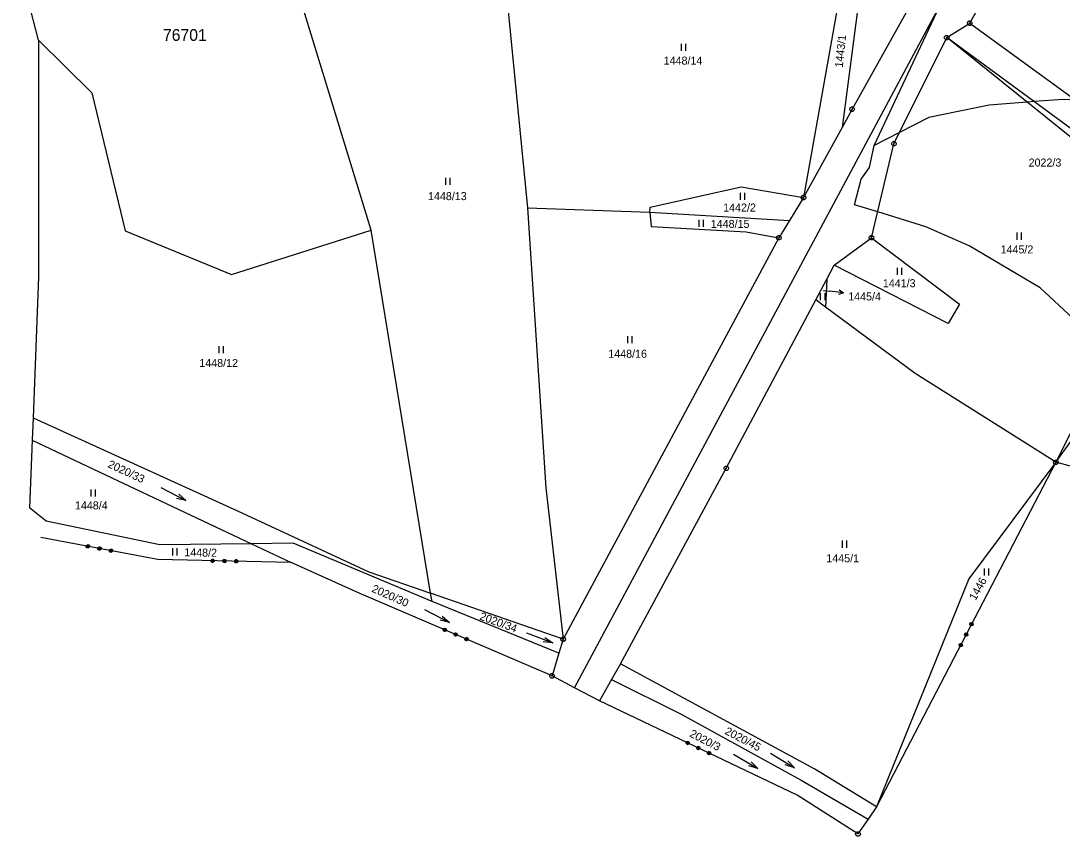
# Model space of a CAD drawing. Extents: x -789470 to -786707, y -1118640 to -1114455.
# Drawn here: x -787437 to -787215.8, y -1118639.9 to -1118466.7 of the extents above; entities that cross this region are included whole.
import ezdxf

# ---------------------------------------------------------------- set-up
doc = ezdxf.new("R2010")
doc.units = 0
for name, color, linetype in [('1', 7, 'Continuous'), ('11', 7, 'Continuous'), ('2', 7, 'Continuous'), ('3', 7, 'Continuous'), ('6', 7, 'Continuous'), ('7', 7, 'Continuous'), ('8', 7, 'Continuous')]:
    doc.layers.add(name, color=color, linetype=linetype)

msp = doc.modelspace()

# ---------------------------------------------------------------- linework, layer by layer
at = {"layer": '1'}
for p, q in [((-787362.53, -1118511.14), (-787390.51, -1118419.78)), ((-787433.19, -1118470.77), (-787443.96, -1118428.82)), ((-787235.39, -1118467.18), (-787217.86, -1118435.86)), ((-787261.35, -1118451.77), (-787270.69, -1118504.24)), ((-787258.06, -1118455.25), (-787262.52, -1118489.37)), ((-787334.09, -1118457.75), (-787329.35, -1118506.42)), ((-787248.91, -1118464.91), (-787260.38, -1118485.47)), ((-787240.28, -1118470.25), (-787235.39, -1118467.18)), ((-787235.39, -1118467.18), (-787210.21, -1118485.49)), ((-787433.19, -1118470.77), (-787433.23, -1118521.06)), ((-787433.19, -1118470.77), (-787421.86, -1118481.96)), ((-787251.49, -1118492.81), (-787240.28, -1118470.25)), ((-787213.6, -1118489.81), (-787240.28, -1118470.25)), ((-787213.08, -1118492.14), (-787240.28, -1118470.25)), ((-787421.86, -1118481.96), (-787414.81, -1118511.34)), ((-787260.38, -1118485.47), (-787262.52, -1118489.37)), ((-787262.52, -1118489.37), (-787270.69, -1118504.24)), ((-787256.27, -1118512.79), (-787251.49, -1118492.81)), ((-787186.43, -1118499.08), (-787217.11, -1118560.49)), ((-787303.28, -1118506.29), (-787283.94, -1118501.92)), ((-787283.94, -1118501.92), (-787270.69, -1118504.24)), ((-787270.69, -1118504.24), (-787273.7, -1118509.14)), ((-787329.35, -1118506.42), (-787303.31, -1118507.31)), ((-787329.35, -1118506.42), (-787325.42, -1118565.9)), ((-787303.31, -1118507.31), (-787303.28, -1118506.29)), ((-787303.31, -1118507.31), (-787303.09, -1118510.36)), ((-787303.31, -1118507.31), (-787273.7, -1118509.14)), ((-787303.09, -1118510.36), (-787282.85, -1118511.55)), ((-787273.7, -1118509.14), (-787275.95, -1118512.79)), ((-787414.81, -1118511.34), (-787392.19, -1118520.57)), ((-787392.19, -1118520.57), (-787362.53, -1118511.14)), ((-787349.9, -1118588.32), (-787362.53, -1118511.14)), ((-787275.95, -1118512.79), (-787321.76, -1118598.1)), ((-787282.85, -1118511.55), (-787275.95, -1118512.79)), ((-787264.16, -1118518.6), (-787256.27, -1118512.79)), ((-787256.27, -1118512.79), (-787237.55, -1118526.92)), ((-787265.75, -1118521.6), (-787264.16, -1118518.6)), ((-787240, -1118531.03), (-787264.16, -1118518.6)), ((-787433.23, -1118521.06), (-787434.36, -1118551.03)), ((-787268.09, -1118526), (-787265.75, -1118521.6)), ((-787265.75, -1118521.6), (-787266.06, -1118527.5)), ((-787287.1, -1118561.77), (-787268.09, -1118526)), ((-787266.06, -1118527.5), (-787268.09, -1118526)), ((-787246.95, -1118541.62), (-787266.06, -1118527.5)), ((-787237.55, -1118526.92), (-787240, -1118531.03)), ((-787217.11, -1118560.49), (-787200.96, -1118538.1)), ((-787217.11, -1118560.49), (-787246.95, -1118541.62)), ((-787434.36, -1118551.03), (-787434.54, -1118555.77)), ((-787434.36, -1118551.03), (-787390.92, -1118570.77)), ((-787434.54, -1118555.77), (-787435.08, -1118570.18)), ((-787434.54, -1118555.77), (-787387.94, -1118577.81)), ((-787309.57, -1118603.31), (-787287.1, -1118561.77)), ((-787217.11, -1118560.49), (-787255.19, -1118633.7)), ((-787217.11, -1118560.49), (-787235.57, -1118585.27)), ((-787213.48, -1118561.45), (-787217.11, -1118560.49)), ((-787325.42, -1118565.9), (-787321.76, -1118598.1)), ((-787431.54, -1118573.02), (-787435.08, -1118570.18)), ((-787390.92, -1118570.77), (-787363.02, -1118583.76)), ((-787407.41, -1118578.04), (-787431.54, -1118573.02)), ((-787407.83, -1118581.15), (-787432.67, -1118576.48)), ((-787387.94, -1118577.81), (-787407.41, -1118578.04)), ((-787379.13, -1118577.71), (-787387.94, -1118577.81)), ((-787387.94, -1118577.81), (-787379.56, -1118581.78)), ((-787349.61, -1118590.09), (-787379.13, -1118577.71)), ((-787379.56, -1118581.78), (-787407.83, -1118581.15)), ((-787365.06, -1118588.3), (-787379.56, -1118581.78)), ((-787363.02, -1118583.76), (-787349.9, -1118588.32)), ((-787235.57, -1118585.27), (-787255.19, -1118633.7)), ((-787324.12, -1118605.87), (-787365.06, -1118588.3)), ((-787349.61, -1118590.09), (-787349.9, -1118588.32)), ((-787321.76, -1118598.1), (-787349.9, -1118588.32)), ((-787322.66, -1118601.06), (-787349.61, -1118590.09)), ((-787321.76, -1118598.1), (-787322.66, -1118601.06)), ((-787322.66, -1118601.06), (-787324.12, -1118605.87)), ((-787309.57, -1118603.31), (-787311.47, -1118606.64)), ((-787268.28, -1118625.73), (-787309.57, -1118603.31)), ((-787319.31, -1118608.45), (-787324.12, -1118605.87)), ((-787311.47, -1118606.64), (-787314.06, -1118611.19)), ((-787311.47, -1118606.64), (-787296.71, -1118614.01)), ((-787314.06, -1118611.19), (-787319.31, -1118608.45)), ((-787272.02, -1118631.21), (-787314.06, -1118611.19)), ((-787296.71, -1118614.01), (-787271.2, -1118628.01)), ((-787255.19, -1118633.7), (-787268.28, -1118625.73)), ((-787271.2, -1118628.01), (-787257, -1118636.34)), ((-787259.14, -1118639.46), (-787272.02, -1118631.21)), ((-787255.19, -1118633.7), (-787257, -1118636.34)), ((-787257, -1118636.34), (-787259.14, -1118639.46))]:
    msp.add_line(p, q, dxfattribs=at)
for points in [[(-787422.91, -1118578.64), (-787423.07, -1118578.42), (-787423.02, -1118578.15), (-787422.79, -1118578), (-787422.53, -1118578.05), (-787422.38, -1118578.27), (-787422.43, -1118578.54), (-787422.65, -1118578.69), (-787422.91, -1118578.64), (-787422.87, -1118578.61), (-787422.63, -1118578.65), (-787422.56, -1118578.59), (-787422.93, -1118578.52), (-787422.99, -1118578.42), (-787422.48, -1118578.52), (-787422.47, -1118578.44), (-787422.98, -1118578.34), (-787422.97, -1118578.26), (-787422.45, -1118578.36), (-787422.43, -1118578.28), (-787422.94, -1118578.19), (-787422.89, -1118578.12), (-787422.48, -1118578.19), (-787422.52, -1118578.1), (-787422.75, -1118578.06)], [(-787420.45, -1118579.1), (-787420.6, -1118578.88), (-787420.55, -1118578.62), (-787420.33, -1118578.46), (-787420.06, -1118578.51), (-787419.91, -1118578.74), (-787419.96, -1118579), (-787420.18, -1118579.15), (-787420.45, -1118579.1), (-787420.43, -1118579.07), (-787420.19, -1118579.11), (-787420.1, -1118579.05), (-787420.49, -1118578.97), (-787420.56, -1118578.88), (-787420.01, -1118578.98), (-787419.99, -1118578.9), (-787420.54, -1118578.8), (-787420.53, -1118578.72), (-787419.98, -1118578.83), (-787419.96, -1118578.75), (-787420.51, -1118578.64), (-787420.42, -1118578.58), (-787420.03, -1118578.65), (-787420.09, -1118578.56), (-787420.33, -1118578.52)], [(-787417.98, -1118579.57), (-787418.13, -1118579.35), (-787418.08, -1118579.08), (-787417.86, -1118578.93), (-787417.59, -1118578.98), (-787417.44, -1118579.2), (-787417.49, -1118579.46), (-787417.71, -1118579.62), (-787417.98, -1118579.57), (-787417.98, -1118579.53), (-787417.75, -1118579.57), (-787417.65, -1118579.51), (-787418.05, -1118579.43), (-787418.09, -1118579.34), (-787417.56, -1118579.44), (-787417.54, -1118579.36), (-787418.07, -1118579.27), (-787418.06, -1118579.19), (-787417.54, -1118579.28), (-787417.53, -1118579.2), (-787418.05, -1118579.11), (-787417.98, -1118579.04), (-787417.56, -1118579.12), (-787417.61, -1118579.03), (-787417.89, -1118578.97)], [(-787396.35, -1118581.73), (-787396.54, -1118581.53), (-787396.53, -1118581.26), (-787396.34, -1118581.08), (-787396.07, -1118581.08), (-787395.88, -1118581.28), (-787395.89, -1118581.55), (-787396.08, -1118581.73), (-787396.35, -1118581.73), (-787396.31, -1118581.69), (-787396.07, -1118581.69), (-787396.01, -1118581.61), (-787396.39, -1118581.6), (-787396.47, -1118581.52), (-787395.95, -1118581.53), (-787395.95, -1118581.45), (-787396.47, -1118581.44), (-787396.46, -1118581.36), (-787395.94, -1118581.37), (-787395.93, -1118581.29), (-787396.45, -1118581.28), (-787396.41, -1118581.2), (-787396, -1118581.21), (-787396.05, -1118581.13), (-787396.29, -1118581.13)], [(-787393.84, -1118581.78), (-787394.03, -1118581.59), (-787394.02, -1118581.32), (-787393.83, -1118581.13), (-787393.56, -1118581.14), (-787393.37, -1118581.33), (-787393.38, -1118581.6), (-787393.57, -1118581.79), (-787393.84, -1118581.78), (-787393.83, -1118581.74), (-787393.59, -1118581.75), (-787393.51, -1118581.67), (-787393.91, -1118581.66), (-787393.99, -1118581.58), (-787393.43, -1118581.59), (-787393.43, -1118581.51), (-787393.99, -1118581.5), (-787393.98, -1118581.42), (-787393.42, -1118581.43), (-787393.42, -1118581.35), (-787393.98, -1118581.34), (-787393.9, -1118581.26), (-787393.5, -1118581.27), (-787393.58, -1118581.19), (-787393.82, -1118581.18)], [(-787391.33, -1118581.84), (-787391.52, -1118581.64), (-787391.51, -1118581.37), (-787391.32, -1118581.19), (-787391.05, -1118581.19), (-787390.86, -1118581.39), (-787390.87, -1118581.66), (-787391.06, -1118581.84), (-787391.33, -1118581.84), (-787391.34, -1118581.8), (-787391.1, -1118581.8), (-787391.02, -1118581.73), (-787391.42, -1118581.72), (-787391.48, -1118581.64), (-787390.94, -1118581.65), (-787390.94, -1118581.57), (-787391.47, -1118581.56), (-787391.47, -1118581.48), (-787390.94, -1118581.49), (-787390.94, -1118581.41), (-787391.47, -1118581.4), (-787391.42, -1118581.32), (-787390.99, -1118581.33), (-787391.06, -1118581.24), (-787391.34, -1118581.24)], [(-787234.77, -1118595.14), (-787235.03, -1118595.22), (-787235.27, -1118595.1), (-787235.35, -1118594.84), (-787235.23, -1118594.6), (-787234.97, -1118594.52), (-787234.73, -1118594.64), (-787234.65, -1118594.9), (-787234.77, -1118595.14), (-787234.81, -1118595.13), (-787234.7, -1118594.92), (-787234.74, -1118594.81), (-787234.92, -1118595.16), (-787235.02, -1118595.18), (-787234.77, -1118594.7), (-787234.84, -1118594.66), (-787235.09, -1118595.13), (-787235.16, -1118595.11), (-787234.92, -1118594.64), (-787234.99, -1118594.6), (-787235.23, -1118595.07), (-787235.28, -1118594.99), (-787235.08, -1118594.61), (-787235.19, -1118594.63), (-787235.31, -1118594.88)], [(-787347.15, -1118596.33), (-787347.25, -1118596.08), (-787347.14, -1118595.84), (-787346.89, -1118595.74), (-787346.65, -1118595.84), (-787346.55, -1118596.09), (-787346.65, -1118596.34), (-787346.9, -1118596.44), (-787347.15, -1118596.33), (-787347.1, -1118596.31), (-787346.88, -1118596.41), (-787346.79, -1118596.36), (-787347.14, -1118596.21), (-787347.18, -1118596.1), (-787346.7, -1118596.31), (-787346.67, -1118596.23), (-787347.15, -1118596.03), (-787347.12, -1118595.96), (-787346.64, -1118596.16), (-787346.6, -1118596.09), (-787347.08, -1118595.89), (-787347.01, -1118595.83), (-787346.63, -1118595.99), (-787346.65, -1118595.9), (-787346.87, -1118595.8)], [(-787344.84, -1118597.32), (-787344.94, -1118597.07), (-787344.84, -1118596.83), (-787344.59, -1118596.73), (-787344.34, -1118596.83), (-787344.24, -1118597.08), (-787344.35, -1118597.33), (-787344.6, -1118597.43), (-787344.84, -1118597.32), (-787344.82, -1118597.29), (-787344.6, -1118597.39), (-787344.49, -1118597.34), (-787344.86, -1118597.19), (-787344.9, -1118597.08), (-787344.39, -1118597.3), (-787344.36, -1118597.23), (-787344.87, -1118597.01), (-787344.84, -1118596.93), (-787344.33, -1118597.15), (-787344.29, -1118597.08), (-787344.81, -1118596.86), (-787344.7, -1118596.82), (-787344.34, -1118596.98), (-787344.38, -1118596.87), (-787344.6, -1118596.78)], [(-787235.93, -1118597.37), (-787236.19, -1118597.45), (-787236.43, -1118597.32), (-787236.51, -1118597.07), (-787236.38, -1118596.83), (-787236.13, -1118596.75), (-787235.89, -1118596.87), (-787235.81, -1118597.13), (-787235.93, -1118597.37), (-787235.96, -1118597.34), (-787235.85, -1118597.13), (-787235.88, -1118597.02), (-787236.07, -1118597.37), (-787236.18, -1118597.41), (-787235.92, -1118596.91), (-787235.99, -1118596.87), (-787236.25, -1118597.37), (-787236.32, -1118597.33), (-787236.06, -1118596.84), (-787236.13, -1118596.8), (-787236.39, -1118597.3), (-787236.42, -1118597.19), (-787236.24, -1118596.83), (-787236.35, -1118596.87), (-787236.46, -1118597.08)], [(-787342.54, -1118598.31), (-787342.64, -1118598.06), (-787342.53, -1118597.82), (-787342.28, -1118597.72), (-787342.03, -1118597.82), (-787341.93, -1118598.07), (-787342.04, -1118598.32), (-787342.29, -1118598.42), (-787342.54, -1118598.31), (-787342.53, -1118598.27), (-787342.31, -1118598.37), (-787342.21, -1118598.33), (-787342.57, -1118598.17), (-787342.6, -1118598.07), (-787342.1, -1118598.28), (-787342.07, -1118598.21), (-787342.56, -1118598), (-787342.53, -1118597.92), (-787342.05, -1118598.13), (-787342.02, -1118598.06), (-787342.5, -1118597.85), (-787342.43, -1118597.8), (-787342.03, -1118597.97), (-787342.06, -1118597.87), (-787342.32, -1118597.75)], [(-787237.09, -1118599.59), (-787237.34, -1118599.67), (-787237.58, -1118599.55), (-787237.67, -1118599.29), (-787237.54, -1118599.05), (-787237.28, -1118598.97), (-787237.04, -1118599.1), (-787236.96, -1118599.35), (-787237.09, -1118599.59), (-787237.11, -1118599.54), (-787236.99, -1118599.33), (-787237.04, -1118599.24), (-787237.21, -1118599.57), (-787237.32, -1118599.61), (-787237.08, -1118599.15), (-787237.15, -1118599.11), (-787237.39, -1118599.57), (-787237.46, -1118599.53), (-787237.22, -1118599.07), (-787237.29, -1118599.03), (-787237.53, -1118599.49), (-787237.58, -1118599.42), (-787237.39, -1118599.05), (-787237.49, -1118599.06), (-787237.6, -1118599.27)], [(-787295.57, -1118620.35), (-787295.66, -1118620.1), (-787295.54, -1118619.85), (-787295.29, -1118619.76), (-787295.05, -1118619.88), (-787294.96, -1118620.13), (-787295.07, -1118620.38), (-787295.33, -1118620.47), (-787295.57, -1118620.35), (-787295.52, -1118620.33), (-787295.3, -1118620.43), (-787295.21, -1118620.39), (-787295.55, -1118620.22), (-787295.59, -1118620.12), (-787295.12, -1118620.34), (-787295.09, -1118620.27), (-787295.56, -1118620.04), (-787295.52, -1118619.97), (-787295.05, -1118620.2), (-787295.01, -1118620.13), (-787295.48, -1118619.9), (-787295.41, -1118619.85), (-787295.04, -1118620.03), (-787295.05, -1118619.93), (-787295.27, -1118619.83)], [(-787293.3, -1118621.43), (-787293.39, -1118621.18), (-787293.28, -1118620.93), (-787293.02, -1118620.84), (-787292.78, -1118620.96), (-787292.69, -1118621.21), (-787292.81, -1118621.45), (-787293.06, -1118621.54), (-787293.3, -1118621.43), (-787293.28, -1118621.4), (-787293.06, -1118621.5), (-787292.95, -1118621.46), (-787293.32, -1118621.29), (-787293.35, -1118621.18), (-787292.85, -1118621.42), (-787292.81, -1118621.35), (-787293.32, -1118621.11), (-787293.28, -1118621.04), (-787292.78, -1118621.28), (-787292.74, -1118621.21), (-787293.25, -1118620.97), (-787293.14, -1118620.93), (-787292.78, -1118621.1), (-787292.82, -1118620.99), (-787293.04, -1118620.89)], [(-787291.04, -1118622.51), (-787291.13, -1118622.25), (-787291.01, -1118622.01), (-787290.76, -1118621.92), (-787290.51, -1118622.04), (-787290.42, -1118622.29), (-787290.54, -1118622.53), (-787290.79, -1118622.62), (-787291.04, -1118622.51), (-787291.03, -1118622.47), (-787290.81, -1118622.57), (-787290.71, -1118622.53), (-787291.07, -1118622.36), (-787291.09, -1118622.26), (-787290.6, -1118622.5), (-787290.57, -1118622.42), (-787291.04, -1118622.2), (-787291.02, -1118622.12), (-787290.54, -1118622.35), (-787290.51, -1118622.27), (-787290.98, -1118622.05), (-787290.9, -1118622), (-787290.52, -1118622.18), (-787290.55, -1118622.08), (-787290.8, -1118621.96)]]:
    msp.add_lwpolyline(points, dxfattribs=at)
at = {"layer": '11'}
for points in [[(-787255.68, -1118493.19), (-787233.59, -1118446.04), (-787230.84, -1118438.51)], [(-787112.79, -1118512.95), (-787130.07, -1118506.17), (-787135.15, -1118504.08), (-787145.45, -1118499.82), (-787158.51, -1118494.43), (-787159.84, -1118493.88), (-787176.24, -1118488.75), (-787197.75, -1118484.31), (-787212.94, -1118483.51), (-787215.54, -1118483.37), (-787221.72, -1118483.85), (-787223.23, -1118483.97), (-787231.26, -1118484.6), (-787244.06, -1118487.19), (-787250.3, -1118490.41), (-787255.68, -1118493.19)], [(-787199.3, -1118569.06), (-787198.55, -1118559.16), (-787201.19, -1118547.24), (-787201.87, -1118545.79), (-787203.36, -1118542.58), (-787203.59, -1118542.09), (-787203.72, -1118541.93), (-787206.27, -1118538.79), (-787213.43, -1118529.96), (-787220.46, -1118523.41), (-787235.48, -1118514.51), (-787244.7, -1118510.43), (-787254.95, -1118507.27), (-787259.84, -1118505.76), (-787258.42, -1118500.3), (-787256.65, -1118497.82), (-787255.68, -1118493.19)], [(-787199.3, -1118569.06), (-787210.97, -1118562.12), (-787213.48, -1118561.45), (-787217.11, -1118560.49), (-787255.19, -1118633.7), (-787257, -1118636.34), (-787259.14, -1118639.46), (-787272.02, -1118631.21), (-787314.06, -1118611.19), (-787319.31, -1118608.45), (-787324.12, -1118605.87), (-787365.06, -1118588.3), (-787379.56, -1118581.78), (-787407.83, -1118581.15), (-787432.67, -1118576.48)]]:
    msp.add_lwpolyline(points, dxfattribs=at)
at = {"layer": '3'}
for p, q in [((-787296.69, -1118471.59), (-787296.69, -1118473.09)), ((-787295.69, -1118473.09), (-787295.69, -1118471.59)), ((-787346.72, -1118500.03), (-787346.72, -1118501.53)), ((-787345.72, -1118501.53), (-787345.72, -1118500.03)), ((-787284.14, -1118503.25), (-787284.14, -1118504.75)), ((-787283.14, -1118504.75), (-787283.14, -1118503.25)), ((-787292.97, -1118508.97), (-787292.97, -1118510.47)), ((-787291.97, -1118510.47), (-787291.97, -1118508.97)), ((-787225.42, -1118511.69), (-787225.42, -1118513.19)), ((-787224.42, -1118513.19), (-787224.42, -1118511.69)), ((-787250.81, -1118519.19), (-787250.81, -1118520.69)), ((-787249.81, -1118520.69), (-787249.81, -1118519.19)), ((-787267.13, -1118524.52), (-787267.13, -1118526.02)), ((-787266.13, -1118526.02), (-787266.13, -1118524.52)), ((-787308.1, -1118533.7), (-787308.1, -1118535.2)), ((-787307.1, -1118535.2), (-787307.1, -1118533.7)), ((-787394.92, -1118535.82), (-787394.92, -1118537.32)), ((-787393.92, -1118537.32), (-787393.92, -1118535.82)), ((-787422.06, -1118566.28), (-787422.06, -1118567.78)), ((-787421.06, -1118567.78), (-787421.06, -1118566.28)), ((-787407.21, -1118565.88), (-787401.87, -1118568.62)), ((-787262.49, -1118577.14), (-787262.49, -1118578.64)), ((-787261.49, -1118578.64), (-787261.49, -1118577.14)), ((-787404.76, -1118578.77), (-787404.76, -1118580.27)), ((-787403.76, -1118580.27), (-787403.76, -1118578.77)), ((-787232.35, -1118583.06), (-787232.35, -1118584.56)), ((-787231.35, -1118584.56), (-787231.35, -1118583.06)), ((-787351.22, -1118591.79), (-787345.9, -1118594.55)), ((-787329.56, -1118596.74), (-787323.94, -1118598.86)), ((-787285.54, -1118622.54), (-787280.38, -1118625.58)), ((-787277.73, -1118622.27), (-787272.61, -1118625.41))]:
    msp.add_line(p, q, dxfattribs=at)
for points in [[(-787403.42, -1118567.26), (-787401.87, -1118568.62), (-787403.88, -1118568.15)], [(-787347.44, -1118593.19), (-787345.9, -1118594.55), (-787347.9, -1118594.07)], [(-787325.64, -1118597.69), (-787323.94, -1118598.86), (-787325.99, -1118598.62)], [(-787281.84, -1118624.14), (-787280.38, -1118625.58), (-787282.35, -1118625)], [(-787274.06, -1118623.94), (-787272.61, -1118625.41), (-787274.58, -1118624.79)]]:
    msp.add_lwpolyline(points, dxfattribs=at)
at = {"layer": '6'}
msp.add_line((-787319.31, -1118608.45), (-787222.61, -1118427.68), dxfattribs=at)
at = {"layer": '7'}
for p in [(-787266.47, -1118523.95), (-787262.22, -1118524.48)]:
    msp.add_line(p, (-787265.2, -1118524.11), dxfattribs=at)
msp.add_lwpolyline([(-787263.15, -1118523.86), (-787262.22, -1118524.48), (-787263.28, -1118524.85)], dxfattribs=at)
at = {"layer": '8'}
for p, q in [((-787235.51, -1118467.18), (-787235.27, -1118467.18)), ((-787240.4, -1118470.25), (-787240.16, -1118470.25)), ((-787260.5, -1118485.47), (-787260.26, -1118485.47)), ((-787251.61, -1118492.81), (-787251.37, -1118492.81)), ((-787270.81, -1118504.24), (-787270.57, -1118504.24)), ((-787276.07, -1118512.79), (-787275.83, -1118512.79)), ((-787256.39, -1118512.79), (-787256.15, -1118512.79)), ((-787287.22, -1118561.77), (-787286.98, -1118561.77)), ((-787217.23, -1118560.49), (-787216.99, -1118560.49)), ((-787321.88, -1118598.1), (-787321.64, -1118598.1)), ((-787324.24, -1118605.87), (-787324, -1118605.87)), ((-787259.02, -1118639.46), (-787259.26, -1118639.46))]:
    msp.add_line(p, q, dxfattribs=at)
for points in [[(-787235.24, -1118466.7), (-787234.99, -1118466.88), (-787234.89, -1118467.17), (-787234.99, -1118467.46), (-787235.24, -1118467.64), (-787235.55, -1118467.64), (-787235.8, -1118467.46), (-787235.9, -1118467.17), (-787235.8, -1118466.88), (-787235.55, -1118466.7)], [(-787240.13, -1118469.77), (-787239.88, -1118469.95), (-787239.78, -1118470.24), (-787239.88, -1118470.53), (-787240.13, -1118470.71), (-787240.44, -1118470.71), (-787240.69, -1118470.53), (-787240.79, -1118470.24), (-787240.69, -1118469.95), (-787240.44, -1118469.77)], [(-787260.23, -1118484.99), (-787259.98, -1118485.17), (-787259.88, -1118485.46), (-787259.98, -1118485.75), (-787260.23, -1118485.93), (-787260.54, -1118485.93), (-787260.79, -1118485.75), (-787260.89, -1118485.46), (-787260.79, -1118485.17), (-787260.54, -1118484.99)], [(-787251.34, -1118492.33), (-787251.09, -1118492.51), (-787250.99, -1118492.8), (-787251.09, -1118493.09), (-787251.34, -1118493.27), (-787251.65, -1118493.27), (-787251.9, -1118493.09), (-787252, -1118492.8), (-787251.9, -1118492.51), (-787251.65, -1118492.33)], [(-787270.54, -1118503.76), (-787270.29, -1118503.94), (-787270.19, -1118504.23), (-787270.29, -1118504.52), (-787270.54, -1118504.7), (-787270.85, -1118504.7), (-787271.1, -1118504.52), (-787271.2, -1118504.23), (-787271.1, -1118503.94), (-787270.85, -1118503.76)], [(-787275.8, -1118512.31), (-787275.55, -1118512.49), (-787275.45, -1118512.78), (-787275.55, -1118513.07), (-787275.8, -1118513.25), (-787276.11, -1118513.25), (-787276.36, -1118513.07), (-787276.46, -1118512.78), (-787276.36, -1118512.49), (-787276.11, -1118512.31)], [(-787256.12, -1118512.31), (-787255.87, -1118512.49), (-787255.77, -1118512.78), (-787255.87, -1118513.07), (-787256.12, -1118513.25), (-787256.43, -1118513.25), (-787256.68, -1118513.07), (-787256.78, -1118512.78), (-787256.68, -1118512.49), (-787256.43, -1118512.31)], [(-787286.95, -1118561.29), (-787286.7, -1118561.47), (-787286.6, -1118561.76), (-787286.7, -1118562.05), (-787286.95, -1118562.23), (-787287.26, -1118562.23), (-787287.51, -1118562.05), (-787287.61, -1118561.76), (-787287.51, -1118561.47), (-787287.26, -1118561.29)], [(-787216.96, -1118560.01), (-787216.71, -1118560.19), (-787216.61, -1118560.48), (-787216.71, -1118560.77), (-787216.96, -1118560.95), (-787217.27, -1118560.95), (-787217.52, -1118560.77), (-787217.62, -1118560.48), (-787217.52, -1118560.19), (-787217.27, -1118560.01)], [(-787321.61, -1118597.62), (-787321.36, -1118597.8), (-787321.26, -1118598.09), (-787321.36, -1118598.38), (-787321.61, -1118598.56), (-787321.92, -1118598.56), (-787322.17, -1118598.38), (-787322.27, -1118598.09), (-787322.17, -1118597.8), (-787321.92, -1118597.62)], [(-787323.97, -1118605.39), (-787323.72, -1118605.57), (-787323.62, -1118605.86), (-787323.72, -1118606.15), (-787323.97, -1118606.33), (-787324.28, -1118606.33), (-787324.53, -1118606.15), (-787324.63, -1118605.86), (-787324.53, -1118605.57), (-787324.28, -1118605.39)], [(-787259.29, -1118639.94), (-787259.54, -1118639.76), (-787259.64, -1118639.47), (-787259.54, -1118639.18), (-787259.29, -1118639), (-787258.98, -1118639), (-787258.73, -1118639.18), (-787258.63, -1118639.47), (-787258.73, -1118639.76), (-787258.98, -1118639.94)]]:
    msp.add_lwpolyline(points, close=True, dxfattribs=at)

# ---------------------------------------------------------------- texts
at = {"layer": '11'}
msp.add_text('76701', height=2.5, dxfattribs=at).set_placement((-787406.76, -1118470.94))
at = {"layer": '2'}
for s, rotation, p in [('1443/1', 84.1102, (-787262.36, -1118476.67)), ('2020/33', 334.9511, (-787418.61, -1118561.48)), ('1448/2', 359.1222, (-787402.24, -1118580.46)), ('1446', 60.6762, (-787234.16, -1118589.97)), ('2020/30', 336.0397, (-787362.56, -1118587.95)), ('2020/34', 339.7067, (-787339.63, -1118593.86)), ('2020/45', 332.3728, (-787287.58, -1118618.15)), ('2020/3', 332.3728, (-787295.05, -1118618.68))]:
    msp.add_text(s, height=1.7, rotation=rotation, dxfattribs=at).set_placement(p)
for s, height, p in [('1448/14', 1.7, (-787300.41, -1118475.98)), ('1448/13', 1.7, (-787350.46, -1118504.78)), ('1442/2', 1.7, (-787287.77, -1118507.2)), ('1448/15', 1.7, (-787290.4, -1118510.68)), ('1445/2', 1.7, (-787228.84, -1118516.1)), ('1441/3', 1.7, (-787253.85, -1118523.28)), ('1445/4', 0.1, (-787266.69, -1118523.95)), ('1448/16', 1.7, (-787312.17, -1118538.28)), ('1448/12', 1.7, (-787399.04, -1118540.24)), ('1448/4', 1.7, (-787425.45, -1118570.5)), ('1445/1', 1.7, (-787265.86, -1118581.74))]:
    msp.add_text(s, height=height, dxfattribs=at).set_placement(p)
at = {"layer": '7'}
for s, p in [('2022/3', (-787222.89, -1118497.64)), ('1445/4', (-787261.21, -1118526.1))]:
    msp.add_text(s, height=1.7, dxfattribs=at).set_placement(p)

doc.saveas('drawing.dxf')
